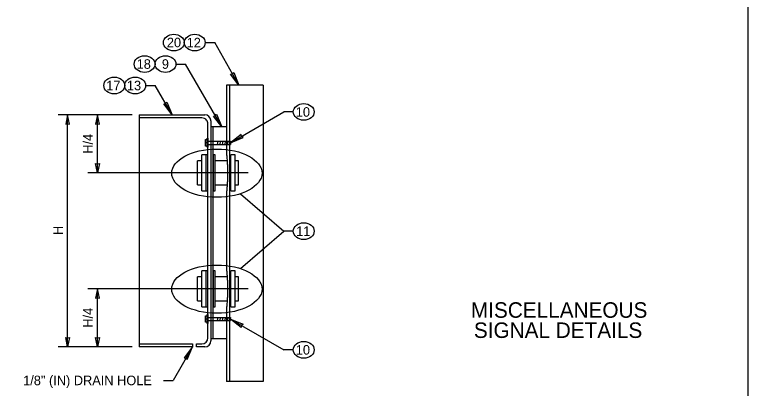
# Model space of a CAD drawing. Extents: x 99862 to 104211, y 98939 to 102076.
# Drawn here: x 101922 to 103151, y 100203 to 100830 of the extents above; entities that cross this region are included whole.
import ezdxf

# ---------------------------------------------------------------- set-up
doc = ezdxf.new("R2010")
doc.units = 0
for name, color, linetype in [('Level 1', 7, 'Continuous'), ('Level 10', 7, 'Continuous'), ('Level 12', 7, 'Continuous'), ('Level 13', 7, 'Continuous'), ('Level 14', 7, 'Continuous'), ('Level 15', 7, 'Continuous'), ('Level 17', 7, 'Continuous'), ('Level 18', 7, 'Continuous'), ('Level 20', 7, 'Continuous'), ('Level 62', 7, 'Continuous')]:
    doc.layers.add(name, color=color, linetype=linetype)

msp = doc.modelspace()

# ---------------------------------------------------------------- linework, layer by layer
at = {"layer": 'Level 1'}
for p, q in [((102281.7, 100711.5), (102281.7, 100214.7)), ((102262.2, 100617.8), (102261.5, 100612.4)), ((102266.4, 100617.8), (102265.7, 100612.4)), ((102270.6, 100617.8), (102269.9, 100612.4)), ((102274.9, 100617.8), (102274.2, 100612.4)), ((102279.1, 100617.8), (102278.4, 100612.4)), ((102262.2, 100322.3), (102261.5, 100317)), ((102266.4, 100322.3), (102265.7, 100317)), ((102270.6, 100322.3), (102269.9, 100317)), ((102274.9, 100322.3), (102274.2, 100317)), ((102279.1, 100322.3), (102278.4, 100317)), ((102283.4, 100322.3), (102282.6, 100317))]:
    msp.add_line(p, q, dxfattribs=at)
msp.add_lwpolyline([(99862, 99999.5), (103151, 99999.5), (103151, 102075.5), (99862, 102075.5)], close=True, dxfattribs=at)
at = {"layer": 'Level 10'}
for p, q in [((102244.8, 100615.1), (102241.5, 100615.1)), ((102245.9, 100617.8), (102283.4, 100617.8)), ((102245.9, 100612.4), (102283.4, 100612.4)), ((102283.4, 100617.8), (102282.6, 100612.4)), ((102283.4, 100617.8), (102283.4, 100612.4)), ((102244.7, 100319.6), (102241.5, 100319.6)), ((102245.9, 100322.3), (102283.4, 100322.3)), ((102245.9, 100317), (102283.4, 100317)), ((102283.4, 100317), (102283.4, 100322.3))]:
    msp.add_line(p, q, dxfattribs=at)
for points in [[(102241.5, 100620.6), (102244.8, 100620.6), (102244.8, 100609.6), (102241.5, 100609.6)], [(102244.8, 100622.6), (102245.9, 100622.6), (102245.9, 100607.5), (102244.8, 100607.5)], [(102241.5, 100325.1), (102244.7, 100325.1), (102244.7, 100314.2), (102241.5, 100314.2)], [(102244.7, 100327.2), (102245.8, 100327.2), (102245.8, 100312), (102244.7, 100312)]]:
    msp.add_lwpolyline(points, close=True, dxfattribs=at)
at = {"layer": 'Level 12'}
for p, q in [((102338.6, 100711.5), (102276.8, 100711.5)), ((102276.8, 100711.5), (102276.8, 100597.3)), ((102338.6, 100711.5), (102338.6, 100214.7)), ((102276.8, 100530.9), (102276.8, 100403.3)), ((102276.8, 100336.9), (102276.8, 100214.7)), ((102338.6, 100214.7), (102276.8, 100214.7))]:
    msp.add_line(p, q, dxfattribs=at)
for points in [[(102276.8, 100597.3), (102276.9, 100597.1), (102276.9, 100596.2), (102277.3, 100593.1), (102277.5, 100590.7), (102277.8, 100586.1), (102278, 100584.4), (102278.2, 100580.8), (102278.3, 100578.9), (102278.5, 100572.8), (102278.6, 100568.5), (102278.6, 100559.7), (102278.5, 100555.4), (102278.3, 100549.4), (102278.2, 100547.5), (102278, 100543.9), (102277.9, 100542.2), (102277.5, 100537.6), (102277.3, 100535.1), (102276.9, 100531.8), (102276.8, 100530.9), (102276.8, 100530.9)], [(102276.8, 100403.3), (102276.8, 100403.2), (102276.9, 100402.3), (102277.3, 100399.1), (102277.5, 100396.6), (102277.8, 100392), (102278, 100390.3), (102278.2, 100386.7), (102278.3, 100384.8), (102278.5, 100378.8), (102278.6, 100374.5), (102278.6, 100365.7), (102278.5, 100361.4), (102278.3, 100355.4), (102278.2, 100353.5), (102278, 100349.8), (102277.9, 100348.1), (102277.5, 100343.5), (102277.3, 100341.1), (102276.9, 100337.8), (102276.8, 100336.9), (102276.8, 100336.9)]]:
    msp.add_open_spline(points, degree=3, dxfattribs=at)
at = {"layer": 'Level 13'}
for p, q in [((102130.8, 100661.8), (102130.8, 100273)), ((102130.8, 100661.8), (102208.6, 100661.8)), ((102208.6, 100661.8), (102211, 100661.8)), ((102211, 100661.8), (102218.3, 100661.8)), ((102218.3, 100661.8), (102229.5, 100661.8)), ((102229.5, 100661.8), (102240.8, 100661.8)), ((102208.6, 100656.8), (102130.8, 100656.8)), ((102211, 100656.8), (102208.6, 100656.8)), ((102218.3, 100656.8), (102211, 100656.8)), ((102229.5, 100656.8), (102218.3, 100656.8)), ((102235.8, 100656.8), (102229.5, 100656.8)), ((102250.8, 100651.8), (102250.8, 100283)), ((102245.8, 100288), (102245.8, 100646.8)), ((102130.8, 100278), (102220, 100278)), ((102220, 100273), (102130.8, 100273)), ((102220, 100278), (102220, 100273)), ((102226.7, 100273), (102226.7, 100278)), ((102226.7, 100278), (102235.8, 100278)), ((102240.8, 100273), (102226.7, 100273))]:
    msp.add_line(p, q, dxfattribs=at)
for centre, start, end in [((102240.8, 100651.8), 6.7496, 90), ((102235.8, 100646.8), 38.1361, 90), ((102235.8, 100646.8), 0, 38.1361), ((102240.8, 100651.8), 0, 6.7496), ((102235.8, 100288), 270, 0), ((102240.8, 100283), 270, 0)]:
    msp.add_arc(centre, 10, start, end, dxfattribs=at)
at = {"layer": 'Level 14'}
for p, q in [((102243.1, 100594.6), (102235.7, 100594.6)), ((102235.7, 100534.6), (102235.7, 100594.6)), ((102291.5, 100594.6), (102284.1, 100594.6)), ((102291.5, 100534.6), (102291.5, 100594.6)), ((102235.7, 100534.6), (102243.1, 100534.6)), ((102284.1, 100534.6), (102291.5, 100534.6)), ((102243.1, 100400.2), (102235.7, 100400.2)), ((102235.7, 100340.2), (102235.7, 100400.2)), ((102284.1, 100340.2), (102284.1, 100400.2)), ((102291.5, 100400.2), (102284.1, 100400.2)), ((102291.5, 100340.2), (102291.5, 100400.2)), ((102235.7, 100340.2), (102243.1, 100340.2)), ((102284.1, 100340.2), (102291.5, 100340.2))]:
    msp.add_line(p, q, dxfattribs=at)
at = {"layer": 'Level 15'}
for p, q in [((102241.2, 100782.9), (102257.2, 100782.9)), ((102297.7, 100711.5), (102257.2, 100782.9)), ((102192.2, 100747), (102208.2, 100747)), ((102269.1, 100641.5), (102208.2, 100747)), ((102141.4, 100711), (102157.4, 100711)), ((102185.8, 100661.8), (102157.4, 100711)), ((102118.8, 100661.8), (101994.8, 100661.8)), ((102010.8, 100273), (102010.8, 100661.8)), ((102060.8, 100564.6), (102060.8, 100661.8)), ((102283.4, 100615.1), (102372.8, 100666.7)), ((102388.8, 100666.7), (102372.8, 100666.7)), ((102313.1, 100564.6), (102044.8, 100564.6)), ((102300.4, 100529.7), (102372.8, 100466.9)), ((102300.4, 100404.1), (102372.8, 100466.9)), ((102388.8, 100466.9), (102372.8, 100466.9)), ((102313.1, 100370.2), (102044.8, 100370.2)), ((102060.8, 100273), (102060.8, 100370.2)), ((102283.4, 100319.6), (102372.8, 100268)), ((102118.8, 100273), (101994.8, 100273)), ((102220, 100273), (102187.5, 100216.7)), ((102388.8, 100268), (102372.8, 100268)), ((102171.5, 100216.7), (102187.5, 100216.7))]:
    msp.add_line(p, q, dxfattribs=at)
for points in [[(102297.7, 100711.5), (102283.8, 100729.8), (102286.9, 100730.4), (102289, 100732.8)], [(102185.8, 100661.8), (102171.8, 100680.1), (102174.9, 100680.7), (102177, 100683.1)], [(102010.8, 100661.8), (102007.7, 100646), (102010.8, 100646.8), (102013.9, 100646)], [(102060.8, 100661.8), (102057.7, 100646), (102060.8, 100646.8), (102063.9, 100646)], [(102269.1, 100641.5), (102255.1, 100659.8), (102258.2, 100660.4), (102260.3, 100662.8)], [(102283.4, 100615.1), (102304.6, 100623.9), (102302.2, 100626), (102301.6, 100629.1)], [(102060.8, 100564.6), (102057.7, 100580.3), (102060.8, 100579.6), (102063.9, 100580.3)], [(102060.8, 100370.2), (102057.7, 100354.4), (102060.8, 100355.2), (102063.9, 100354.4)], [(102283.4, 100319.6), (102304.6, 100310.8), (102302.2, 100308.8), (102301.6, 100305.6)], [(102010.8, 100273), (102007.7, 100288.7), (102010.8, 100288), (102013.9, 100288.7)], [(102060.8, 100273), (102057.7, 100288.7), (102060.8, 100288), (102063.9, 100288.7)], [(102220, 100273), (102206, 100254.7), (102209.2, 100254.1), (102211.2, 100251.7)]]:
    msp.add_lwpolyline(points, close=True, dxfattribs=at)
for centre in [(102260.8, 100564.1), (102260.8, 100369.7)]:
    msp.add_ellipse(centre, major_axis=(75.6, 0), ratio=0.534017, dxfattribs=at)
at = {"layer": 'Level 17'}
for p, q in [((102245.6, 100594.6), (102243.1, 100594.6)), ((102243.1, 100534.6), (102243.1, 100594.6)), ((102245.6, 100534.6), (102245.6, 100594.6)), ((102257.7, 100594.6), (102255.2, 100594.6)), ((102255.2, 100534.6), (102255.2, 100594.6)), ((102257.7, 100534.6), (102257.7, 100594.6)), ((102284.1, 100534.6), (102284.1, 100594.6)), ((102243.1, 100534.6), (102245.6, 100534.6)), ((102255.2, 100534.6), (102257.7, 100534.6)), ((102245.6, 100400.2), (102243.1, 100400.2)), ((102243.1, 100340.2), (102243.1, 100400.2)), ((102245.6, 100340.2), (102245.6, 100400.2)), ((102257.7, 100400.2), (102255.2, 100400.2)), ((102255.2, 100340.2), (102255.2, 100400.2)), ((102257.7, 100340.2), (102257.7, 100400.2)), ((102243.1, 100340.2), (102245.6, 100340.2)), ((102255.2, 100340.2), (102257.7, 100340.2))]:
    msp.add_line(p, q, dxfattribs=at)
at = {"layer": 'Level 18'}
for p, q in [((102228.3, 100544.6), (102228.3, 100584.6)), ((102235.7, 100584.6), (102228.3, 100584.6)), ((102255.2, 100584.6), (102254.6, 100584.6)), ((102277.9, 100584.6), (102257.7, 100584.6)), ((102284.1, 100584.6), (102281.7, 100584.6)), ((102297.1, 100584.6), (102291.5, 100584.6)), ((102297.1, 100544.6), (102297.1, 100584.6)), ((102228.3, 100544.6), (102235.7, 100544.6)), ((102254.6, 100544.6), (102255.2, 100544.6)), ((102257.7, 100544.6), (102278, 100544.6)), ((102281.7, 100544.6), (102284.1, 100544.6)), ((102291.5, 100544.6), (102297.1, 100544.6)), ((102228.3, 100350.2), (102228.3, 100390.2)), ((102235.7, 100390.2), (102228.3, 100390.2)), ((102255.2, 100390.2), (102254.6, 100390.2)), ((102278, 100390.2), (102257.7, 100390.2)), ((102284.1, 100390.2), (102281.7, 100390.2)), ((102297.1, 100390.2), (102291.5, 100390.2)), ((102297.1, 100350.2), (102297.1, 100390.2)), ((102228.3, 100350.2), (102235.7, 100350.2)), ((102254.6, 100350.2), (102255.2, 100350.2)), ((102257.7, 100350.2), (102278, 100350.2)), ((102281.7, 100350.2), (102284.1, 100350.2)), ((102291.5, 100350.2), (102297.1, 100350.2))]:
    msp.add_line(p, q, dxfattribs=at)
at = {"layer": 'Level 20'}
for p, q in [((102250.8, 100641.5), (102250.8, 100286.5)), ((102254.6, 100641.5), (102250.8, 100641.5)), ((102254.6, 100286.5), (102254.6, 100641.5)), ((102259.7, 100641.5), (102254.6, 100641.5)), ((102276.8, 100641.5), (102259.7, 100641.5)), ((102254.6, 100286.5), (102250.8, 100286.5)), ((102259.7, 100286.5), (102254.6, 100286.5)), ((102276.8, 100286.5), (102259.7, 100286.5))]:
    msp.add_line(p, q, dxfattribs=at)
for centre in [(102188.7, 100782.9), (102223.7, 100782.9), (102139.7, 100747), (102174.7, 100747), (102088.9, 100711), (102123.9, 100711), (102406.3, 100666.7), (102406.3, 100466.9), (102406.3, 100268)]:
    msp.add_ellipse(centre, major_axis=(-17.5, 0), ratio=0.8, dxfattribs=at)

# ---------------------------------------------------------------- texts
for s, p in [('20', (102177, 100775.1)), ('12', (102210.2, 100774.9)), ('18', (102126.4, 100739)), ('9', (102168.6, 100739)), ('17', (102075.5, 100703)), ('13', (102110.1, 100703)), ('10', (102393, 100658.7)), ('11', (102393.6, 100458.9)), ('10', (102393, 100260)), ('1/8" (IN) DRAIN HOLE', (101936.3, 100208.7))]:
    msp.add_text(s, height=16, dxfattribs=at).set_placement(p)
for s, p in [('H/4', (102052.8, 100596.7)), ('H', (102002.8, 100460.4)), ('H/4', (102052.8, 100305.1))]:
    msp.add_text(s, height=16, rotation=90, dxfattribs=at).set_placement(p)
at = {"layer": 'Level 62'}
for s, p in [('MISCELLANEOUS', (102686.3, 100321.7)), ('SIGNAL DETAILS', (102691.3, 100287.9))]:
    msp.add_text(s, height=26, dxfattribs=at).set_placement(p)

doc.saveas('drawing.dxf')
